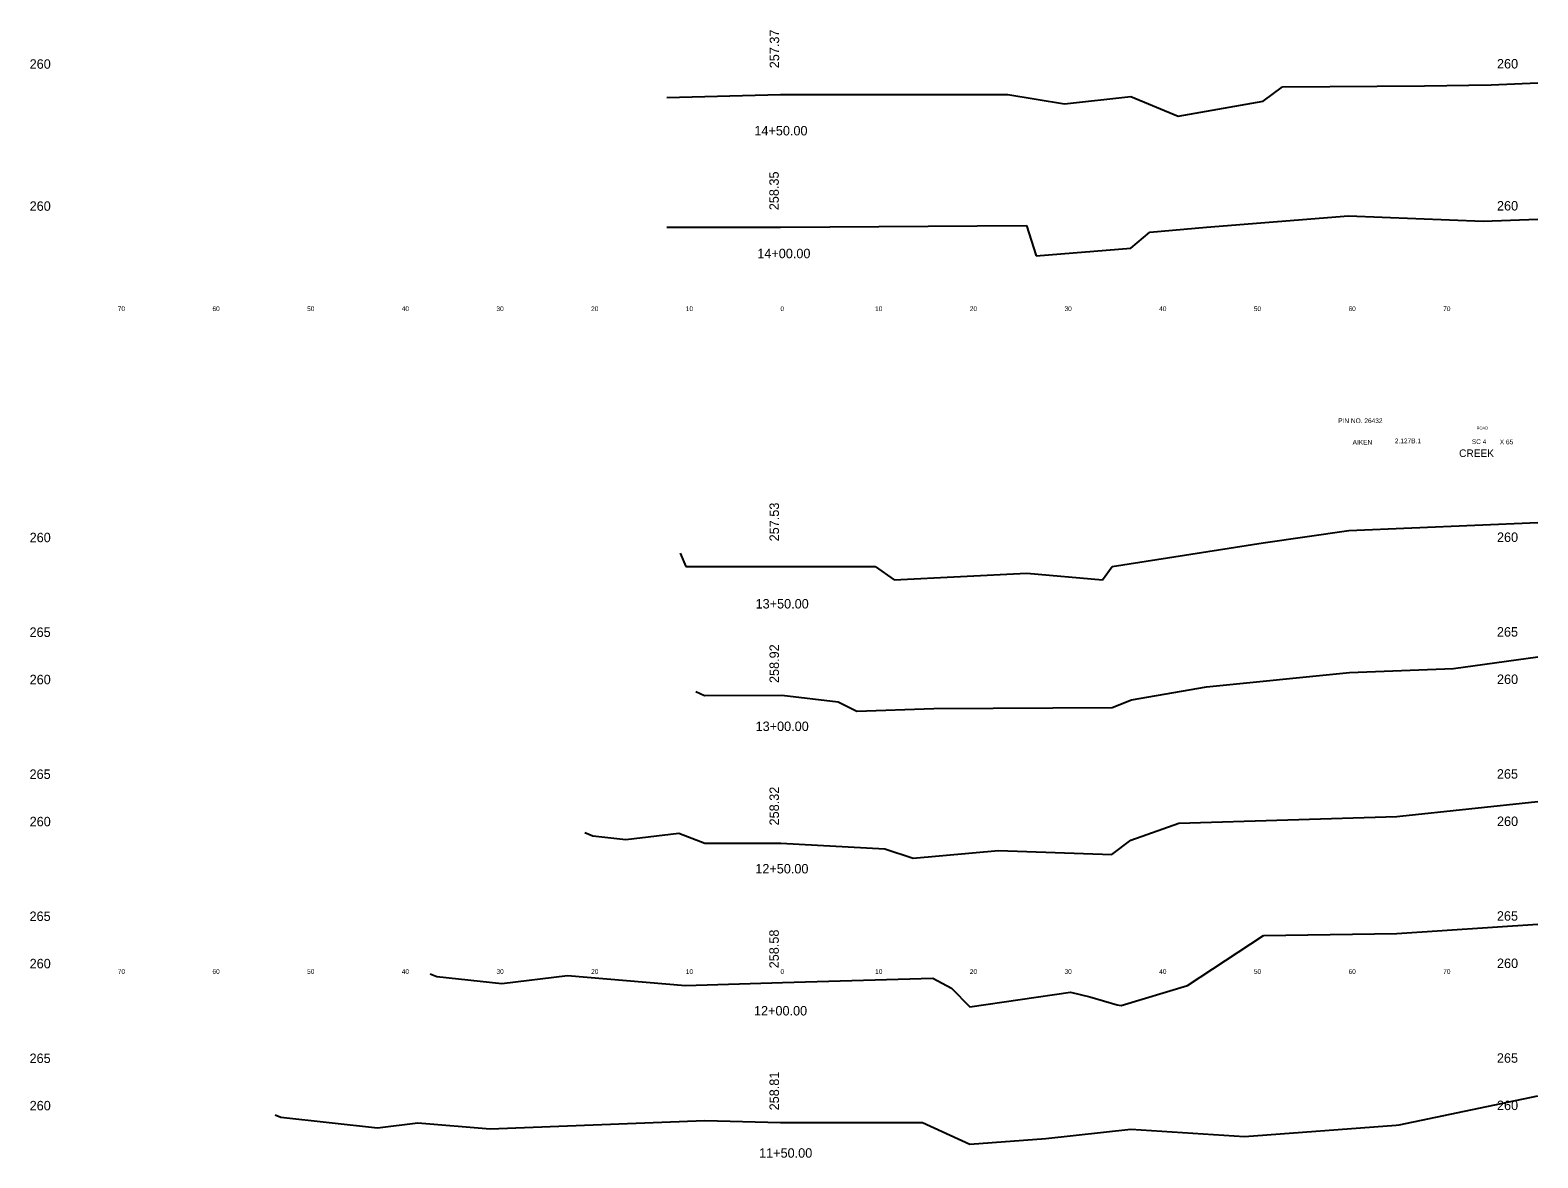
# Model space of a CAD drawing. Extents: x 175484 to 175644, y 176972 to 177478.
# Drawn here: x 175484.9 to 175644.1, y 177227.9 to 177347 of the extents above; entities that cross this region are included whole.
import ezdxf

# ---------------------------------------------------------------- set-up
doc = ezdxf.new("R2010")
doc.units = 0
for name, color, linetype in [('Level 1', 7, 'Continuous'), ('Level 10', 7, 'Continuous'), ('Level 2', 7, 'Continuous'), ('Level 3', 7, 'Continuous'), ('Level 60', 7, 'Continuous')]:
    doc.layers.add(name, color=color, linetype=linetype)

msp = doc.modelspace()

# ---------------------------------------------------------------- linework, layer by layer
at = {"layer": 'Level 60'}
for p, q in [((175615.11, 177339.47), (175617.15, 177340.97)), ((175617.15, 177340.97), (175632.14, 177341.07)), ((175632.14, 177341.07), (175639.18, 177341.18)), ((175639.18, 177341.18), (175644.13, 177341.41)), ((175552.13, 177339.87), (175564.13, 177340.17)), ((175564.13, 177340.17), (175588.15, 177340.17)), ((175588.15, 177340.17), (175594.14, 177339.17)), ((175594.14, 177339.17), (175601.13, 177339.97)), ((175601.13, 177339.97), (175606.12, 177337.88)), ((175606.12, 177337.88), (175615.11, 177339.47)), ((175564.13, 177326.15), (175590.13, 177326.35)), ((175590.13, 177326.35), (175591.13, 177323.15)), ((175609.13, 177326.15), (175624.13, 177327.35)), ((175624.13, 177327.35), (175638.36, 177326.81)), ((175638.36, 177326.81), (175644.13, 177327)), ((175552.13, 177326.15), (175564.13, 177326.15)), ((175601.13, 177323.95), (175603.13, 177325.65)), ((175603.13, 177325.65), (175609.13, 177326.15)), ((175591.13, 177323.15), (175601.13, 177323.95)), ((175624.18, 177294.14), (175644.13, 177294.96)), ((175599.15, 177290.34), (175615.12, 177292.83)), ((175615.12, 177292.83), (175624.18, 177294.14)), ((175553.55, 177291.74), (175554.13, 177290.34)), ((175554.13, 177290.34), (175564.16, 177290.34)), ((175564.16, 177290.34), (175574.14, 177290.34)), ((175574.14, 177290.34), (175576.13, 177288.93)), ((175576.13, 177288.93), (175590.15, 177289.63)), ((175590.15, 177289.63), (175598.13, 177288.93)), ((175598.13, 177288.93), (175599.15, 177290.34)), ((175635.22, 177279.57), (175644.13, 177280.79)), ((175609.13, 177277.62), (175624.25, 177279.13)), ((175624.25, 177279.13), (175635.22, 177279.57)), ((175555.18, 177277.13), (175556.11, 177276.72)), ((175601.21, 177276.24), (175609.13, 177277.62)), ((175556.11, 177276.72), (175564.26, 177276.73)), ((175564.26, 177276.73), (175570.21, 177276.03)), ((175570.21, 177276.03), (175572.19, 177275.04)), ((175572.19, 177275.04), (175580.32, 177275.32)), ((175580.32, 177275.32), (175599.15, 177275.43)), ((175599.15, 177275.43), (175601.21, 177276.24)), ((175629.55, 177263.96), (175644.13, 177265.52)), ((175601.15, 177261.42), (175606.19, 177263.22)), ((175606.19, 177263.22), (175629.23, 177263.94)), ((175629.23, 177263.94), (175629.55, 177263.96)), ((175543.46, 177262.23), (175544.31, 177261.88)), ((175544.31, 177261.88), (175547.8, 177261.5)), ((175547.8, 177261.5), (175553.38, 177262.18)), ((175553.38, 177262.18), (175556.15, 177261.12)), ((175556.15, 177261.12), (175564.15, 177261.12)), ((175564.15, 177261.12), (175575.14, 177260.52)), ((175599.14, 177259.92), (175601.15, 177261.42)), ((175575.14, 177260.52), (175578.14, 177259.52)), ((175578.14, 177259.52), (175587.16, 177260.32)), ((175587.16, 177260.32), (175599.14, 177259.92)), ((175615.16, 177251.37), (175629.25, 177251.58)), ((175629.25, 177251.58), (175644.13, 177252.54)), ((175607.12, 177246.08), (175615.16, 177251.37)), ((175527.11, 177247.32), (175527.82, 177247.03)), ((175527.82, 177247.03), (175534.69, 177246.28)), ((175534.69, 177246.28), (175541.63, 177247.13)), ((175541.63, 177247.13), (175554.1, 177246.08)), ((175564.33, 177246.39), (175580.23, 177246.85)), ((175580.23, 177246.85), (175582.18, 177245.78)), ((175554.1, 177246.08), (175564.33, 177246.39)), ((175582.18, 177245.78), (175584.14, 177243.82)), ((175584.14, 177243.82), (175594.77, 177245.37)), ((175594.77, 177245.37), (175596.81, 177244.89)), ((175600.13, 177243.98), (175607.12, 177246.08)), ((175596.81, 177244.89), (175599.7, 177244.02)), ((175599.7, 177244.02), (175600.13, 177243.98)), ((175629.48, 177231.38), (175644.13, 177234.43)), ((175510.76, 177232.41), (175511.34, 177232.18)), ((175511.34, 177232.18), (175521.58, 177231.06)), ((175521.58, 177231.06), (175525.81, 177231.58)), ((175525.81, 177231.58), (175533.46, 177230.94)), ((175533.46, 177230.94), (175556.14, 177231.81)), ((175556.14, 177231.81), (175564.13, 177231.61)), ((175564.13, 177231.61), (175579.13, 177231.61)), ((175579.13, 177231.61), (175584.14, 177229.31)), ((175592.15, 177229.91), (175601.15, 177230.92)), ((175601.15, 177230.92), (175613.14, 177230.12)), ((175613.14, 177230.12), (175629.15, 177231.32)), ((175629.15, 177231.32), (175629.48, 177231.38)), ((175584.14, 177229.31), (175592.15, 177229.91))]:
    msp.add_line(p, q, dxfattribs=at)

# ---------------------------------------------------------------- texts
at = {"layer": 'Level 1'}
for s, height, p in [('PIN NO. 26432', 0.5, (175623.04, 177305.47)), ('ROAD', 0.3, (175637.66, 177304.8)), ('AIKEN', 0.5, (175624.56, 177303.2)), (' 2.127B.1', 0.5, (175628.83, 177303.34)), ('CREEK', 0.8, (175635.81, 177301.89)), ('SC 4', 0.5, (175637.15, 177303.26)), ('X 65', 0.5, (175640.11, 177303.23))]:
    msp.add_text(s, height=height, dxfattribs=at).set_placement(p)
at = {"layer": 'Level 10'}
for s, p in [('257.37', (175563.99, 177342.94)), ('258.35', (175563.95, 177327.95)), ('257.53', (175563.97, 177292.98)), ('258.92', (175563.97, 177278.02)), ('258.32', (175563.97, 177262.98)), ('258.58', (175563.95, 177247.89)), ('258.81', (175563.97, 177232.89))]:
    msp.add_text(s, height=1, rotation=90, dxfattribs=at).set_placement(p)
for s, p in [('14+50.00', (175561.37, 177335.85)), ('14+00.00', (175561.68, 177322.88)), ('13+50.00', (175561.5, 177285.89)), ('13+00.00', (175561.5, 177272.95)), ('12+50.00', (175561.47, 177257.91)), ('12+00.00', (175561.33, 177242.91)), ('11+50.00', (175561.87, 177227.89))]:
    msp.add_text(s, height=1, dxfattribs=at).set_placement(p)
at = {"layer": 'Level 2'}
for s, p in [('70', (175494.13, 177317.3)), ('60', (175504.13, 177317.3)), ('50', (175514.13, 177317.3)), ('40', (175524.13, 177317.3)), ('30', (175534.13, 177317.3)), ('20', (175544.13, 177317.3)), ('10', (175554.13, 177317.3)), ('0', (175564.13, 177317.3)), ('10', (175574.13, 177317.3)), ('20', (175584.13, 177317.3)), ('30', (175594.13, 177317.3)), ('40', (175604.13, 177317.3)), ('50', (175614.13, 177317.3)), ('60', (175624.13, 177317.3)), ('70', (175634.13, 177317.3)), ('70', (175494.13, 177247.3)), ('60', (175504.13, 177247.3)), ('50', (175514.13, 177247.3)), ('40', (175524.13, 177247.3)), ('30', (175534.13, 177247.3)), ('20', (175544.13, 177247.3)), ('10', (175554.13, 177247.3)), ('0', (175564.13, 177247.3)), ('10', (175574.13, 177247.3)), ('20', (175584.13, 177247.3)), ('30', (175594.13, 177247.3)), ('40', (175604.13, 177247.3)), ('50', (175614.13, 177247.3)), ('60', (175624.13, 177247.3)), ('70', (175634.13, 177247.3))]:
    msp.add_text(s, height=0.5, dxfattribs=at).set_placement(p)
at = {"layer": 'Level 3'}
for s, p in [(' 260', (175484.45, 177342.89)), (' 260', (175639.44, 177342.92)), (' 260', (175484.45, 177327.89)), (' 260', (175639.44, 177327.92)), (' 260', (175484.45, 177292.89)), (' 260', (175639.44, 177292.92)), (' 265', (175484.44, 177282.89)), (' 265', (175639.43, 177282.92)), (' 260', (175484.45, 177277.89)), (' 260', (175639.44, 177277.92)), (' 265', (175484.44, 177267.89)), (' 265', (175639.43, 177267.92)), (' 260', (175484.45, 177262.89)), (' 260', (175639.44, 177262.92)), (' 265', (175484.44, 177252.89)), (' 265', (175639.43, 177252.92)), (' 260', (175484.45, 177247.89)), (' 260', (175639.44, 177247.92)), (' 265', (175484.44, 177237.89)), (' 265', (175639.43, 177237.92)), (' 260', (175484.45, 177232.89)), (' 260', (175639.44, 177232.92))]:
    msp.add_text(s, height=1, dxfattribs=at).set_placement(p)

doc.saveas('drawing.dxf')
